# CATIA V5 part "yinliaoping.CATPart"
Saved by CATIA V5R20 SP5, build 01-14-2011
Part number: 饮料瓶
Material "Blue": density 7860 kg/m3, Young's modulus 2e+11 Pa, Poisson ratio 0.266
Bounding box of the stored display mesh (mm): x -25 to 25, y -25 to 26, z 0 to 110
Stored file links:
  E:\dzy\yinliaoping.CATPart
  C:\Program Files\Dassault Systemes\B20\intel_a\startup\materials\Catalog.CATMaterial
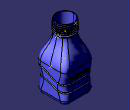
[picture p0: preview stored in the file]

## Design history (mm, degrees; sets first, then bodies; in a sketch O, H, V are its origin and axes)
Set1
  Sketch1 on xy-plane, origin (0, 0, 0), H (1, 0, 0), V (0, 1, 0)
    line L1 (25, 25) -> (25, -25)
    line L2 (25, -25) -> (-25, -25)
    line L3 (-25, -25) -> (-25, 25)
    line L4 (-25, 25) -> (25, 25)
    distance L2 L4 = 50
    distance L1 L3 = 50
    vertical: L1 V, L3 V
    horizontal: L2 H, L4 H
    equidistance: L1 L3 O, L2 L4 O
  Sketch2 on face of Pad1 from Sketch1.L1, origin (25, 0, 0), H (0, 1, 0), V (0, 0, 1)
    spline S1 through (-35.5912, 18.8175) (-8.7243, 27.6787) (10.0624, 21.8383) (42.5855, 25.262)
  Extrude1: Element1 Sketch2, Lim1 61, Lim2 0
  MultiSel1: CommonCtxFeats ({extract ExtractElem face of Pad1 from Sketch1.L1}; {extract ExtractElem face of Fillet1}; {extract ExtractElem face of Pad1 from Sketch1.L4}; {extract ExtractElem face of Fillet1}; {extract ExtractElem face of Pad1 from Sketch1.L3}; {extract ExtractElem face of Fillet1}; {extract ExtractElem face of Pad1 from Sketch1.L2}; {extract ExtractElem face of Fillet1})
  Sketch3 on face of Pad1 from Sketch1.L1, origin (25, 0, 0), H (0, 1, 0), V (0, 0, 1)
    spline S1 through (-41.654, 32.9508) (-13.948, 42.158) (11.3488, 31.95) (40.6609, 43.3589)
  Extrude2: Element1 Sketch3, Lim1 64, Lim2 64
  MultiSel2: CommonCtxFeats ({extract ExtractElem face of Pad1 from Sketch1.L1}; {extract ExtractElem face of Fillet1}; {extract ExtractElem face of Pad1 from Sketch1.L4}; {extract ExtractElem face of Fillet1}; {extract ExtractElem face of Pad1 from Sketch1.L3}; {extract ExtractElem face of Fillet1}; {extract ExtractElem face of Pad1 from Sketch1.L2}; {extract ExtractElem face of Fillet1})
  Join1: Elements ({intersect ToIntersect1 {extract ExtractElem face of Pad1 from Sketch1.L1}, ToIntersect2 Extrude2}; {intersect ToIntersect1 {extract ExtractElem face of Fillet1}, ToIntersect2 Extrude2}; {intersect ToIntersect1 {extract ExtractElem face of Pad1 from Sketch1.L4}, ToIntersect2 Extrude2}; {intersect ToIntersect1 {extract ExtractElem face of Fillet1}, ToIntersect2 Extrude2}; {intersect ToIntersect1 {extract ExtractElem face of Pad1 from Sketch1.L3}, ToIntersect2 Extrude2}; {intersect ToIntersect1 {extract ExtractElem face of Fillet1}, ToIntersect2 Extrude2}; {intersect ToIntersect1 {extract ExtractElem face of Pad1 from Sketch1.L2}, ToIntersect2 Extrude2}; {intersect ToIntersect1 {extract ExtractElem face of Fillet1}, ToIntersect2 Extrude2})
  Join2: Elements ({intersect ToIntersect1 {extract ExtractElem face of Pad1 from Sketch1.L1}, ToIntersect2 Extrude1}; {intersect ToIntersect1 {extract ExtractElem face of Fillet1}, ToIntersect2 Extrude1}; {intersect ToIntersect1 {extract ExtractElem face of Pad1 from Sketch1.L4}, ToIntersect2 Extrude1}; {intersect ToIntersect1 {extract ExtractElem face of Fillet1}, ToIntersect2 Extrude1}; {intersect ToIntersect1 {extract ExtractElem face of Pad1 from Sketch1.L3}, ToIntersect2 Extrude1}; {intersect ToIntersect1 {extract ExtractElem face of Fillet1}, ToIntersect2 Extrude1}; {intersect ToIntersect1 {extract ExtractElem face of Pad1 from Sketch1.L2}, ToIntersect2 Extrude1}; {intersect ToIntersect1 {extract ExtractElem face of Fillet1}, ToIntersect2 Extrude1})
  Plane1: type Normal, Curve Join1, RefPoint vertex [face of MultiSel2 | face of MultiSel2]
  Circle1: type CtrRad, Start 0, End 180, Center vertex [face of MultiSel2 | face of MultiSel2], Support Plane1, Radius 1, FirstDirection (-1, 0, 0)
Body1 (main body), material "Blue"
  Pad1: profile Sketch1, direction (0, 0, 1), length 50
  Fillet1: on edge [face of Pad1 from Sketch1.L2 | face of Pad1 from Sketch1.L3]; edge [face of Pad1 from Sketch1.L1 | face of Pad1 from Sketch1.L2]; edge [face of Pad1 from Sketch1.L3 | face of Pad1 from Sketch1.L4]; edge [face of Pad1 from Sketch1.L4 | face of Pad1 from Sketch1.L1]
  Fillet2: radius 8, on start face of Pad1
  Plane2: type Offset, RefPlane end face of Pad1, Offset 40, reversed
  Sketch4 on Plane2, origin (0, 0, 90), H (1, 0, 0), V (0, -1, 0)
    circle A1 centre (0, 0) radius 15
    radius A1 = 15
  Pad2: profile Sketch4, direction (0, 0, 1), length 20
  Sketch5 on end face of Pad1, origin (0, 0, 50), H (1, 0, 0), V (0, 1, 0)
    point P1 (25, 0)
    distance P1 V = 25
    coincidence: P1 H
  Sketch6 on Plane2, origin (0, 0, 90), H (1, 0, 0), V (0, -1, 0)
    point P1 (15, 0)
    distance P1 V = 15
    coincidence: P1 H
  Loft1: solid, Sections ({boundary Boundary {extract ExtractElem end face of Pad1}}; {boundary Boundary {extract ExtractElem start face of Pad2}}), StartFace end face of Pad1, EndFace start face of Pad2
  Slot1: profile Circle1, centre curve Join1
  Plane3: type Normal, Curve Join2, RefPoint vertex [face of MultiSel1 | face of MultiSel1]
  Circle2: type CtrRad, Start 0, End 180, Center vertex [face of MultiSel1 | face of MultiSel1], Support Plane3, Radius 1, FirstDirection (-1, 0, 0)
  Slot2: profile Circle2, centre curve Join2
  Shell1: ExtOffset 0, Face end face of Pad2, IntOffset 1
  Sketch7 on Plane2, origin (0, 0, 90), H (1, 0, 0), V (0, -1, 0)
    circle A1 centre (0, 0) radius 15
    radius A1 = 15
  Plane4: type Offset, RefPlane Plane2, Offset -2
  Sketch8 on Plane4, origin (0, 0, 92), H (1, 0, 0), V (0, -1, 0)
    circle A1 centre (0, 0) radius 15
    point P1 (15, 0)
    radius A1 = 15
    distance P1 O = 15
    coincidence: P1 H
  Helix1: Direction Z axis, RefPoint Sketch8.P1, Pitch 3, Height 16, TaperAngle 0
  Point1: type OnCurve, Support Helix1, Length -5, RefPoint vertex of Helix1
  Line1: type PtDir, RefPoint vertex of Helix1, Direction (0, 1, 0), Start 0, End -5
  Point2: type OnCurve, Support Helix1, Length 5
  Line2: type PtDir, RefPoint vertex of Helix1, Direction (1, 0, 0), Start 0, End -5
  Connect1: Curve1 Line1, Point1 vertex of Line1, Tension1 1, Curve2 Helix1, Point2 Point1, Tension2 1
  Connect2: Curve1 Line2, Point1 vertex of Line2, Tension1 1, Curve2 Connect1, Point2 Point2, Tension2 1
  Plane5: type Normal, Curve Connect2, RefPoint vertex of Connect2
  Circle3: type CtrRad, Start 0, End 180, Radius 1, Center vertex of Connect2, Support Plane5, FirstDirection (0, 1, 0)
  Rib1: profile Circle3, centre curve Connect2
  Sketch9 on Plane4, origin (0, 0, 92), H (1, 0, 0), V (0, -1, 0)
    circle A1 centre (0, 0) radius 14
    radius A1 = 14
  Pocket1: profile Sketch9, direction (0, 0, 1), length 20, mirrored extent
Body2
  Sketch10 on face of Pad1 from Sketch1.L4, origin (0, 25, 0), H (-1, 0, 0), V (0, 0, 1)
    polyline C1
    polyline C2
    polyline C3
    polyline C4
    polyline C5
    polyline C6
    polyline C7
    polyline C8
    polyline C9
    polyline C10
    polyline C11
  Pad3: profile Sketch10, direction (0, 1, 0), length 1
